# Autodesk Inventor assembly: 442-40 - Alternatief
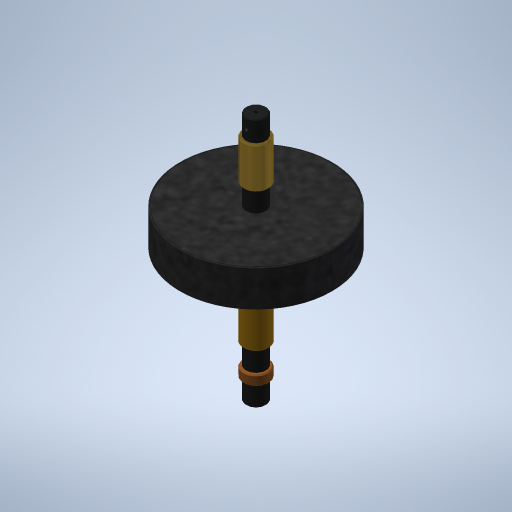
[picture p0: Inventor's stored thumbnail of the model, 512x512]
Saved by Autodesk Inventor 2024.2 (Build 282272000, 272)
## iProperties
Manager: Filip
Company: DARK
Created: 2022-10
Part Number: 442-40 - Alternatief
Document SubType Name: Assembly
Designer: Manuel
Engineer: Filip
Project: 442 - TOTM
Description: TOTM SMALL Assy
Author: Manuel
Revision Number: v0
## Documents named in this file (16)
- C:\Users\Stage\Desktop\Stage Karsten\armatures\TOTM - Wall\442_KARSTEN\3D_LIB_TOTM_2.iam
- C:\Users\Stage\Desktop\Stage Karsten\armatures\TOTM - Wall\442-042.ipt
- C:\Users\Stage\Desktop\Stage Karsten\armatures\TOTM - Wall\442-043.ipt
- C:\Users\Stage\Desktop\Stage Karsten\armatures\TOTM - Wall\442-044.ipt
- C:\Users\Stage\Desktop\Stage Karsten\armatures\TOTM - Wall\442-045.ipt
- C:\Users\Stage\Desktop\Stage Karsten\armatures\TOTM - Wall\442-048.ipt
- C:\Users\Stage\Desktop\Stage Karsten\armatures\TOTM - Wall\442-049.ipt
- C:\Users\Stage\Desktop\Stage Karsten\armatures\TOTM - Wall\442-050.ipt
- C:\Users\Stage\Desktop\Stage Karsten\armatures\TOTM - Wall\442-053.ipt
- C:\Users\Stage\Desktop\Stage Karsten\armatures\TOTM - Wall\442-054.ipt
- C:\Users\Stage\Desktop\Stage Karsten\armatures\TOTM - Wall\442-055.ipt
- C:\Users\Stage\Desktop\Stage Karsten\armatures\TOTM - Wall\442-056.ipt
- N:\LIBRARY\LAMPEN\LED\STARK CLE 120-2200 classic _ 16206616_00.ipt
- N:\LIBRARY\BEVESTIGING\DIN 912\DIN 912 M3 x 8.ipt
- N:\LIBRARY\BEVESTIGING\DIN 985\DIN 985 M3.ipt
- C:\Users\Stage\Desktop\Stage Karsten\armatures\TOTM - Wall\442-40 - Alternatief.iam
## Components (20 placed, 14 different names)
1. 442-042:1 — Mate:19, Mate:20, Mate:21, Mate:22
2. 442-043:1 — Mate:13, Mate:14, Mate:15, Mate:16
3. 442-044:1 — Mate:9, Mate:10, Mate:17, Mate:18
4. 442-045:1 — Mate:23, Mate:24, Mate:32, Mate:34
5. 442-048:1 — Mate:17, Mate:18, Mate:19, Mate:20
6. 442-049:1 — Mate:15, Mate:16
7. 442-050:1 — Mate:21, Mate:22, Mate:23, Mate:24
8. 442-048:2 — Mate:13, Mate:14, Mate:33, Mate:34, Mate:37
9. 442-048:3 — Mate:9, Mate:10, Mate:31
10. 442-053:1
11. 442-054:1 — Mate:28, Flush:1, Mate:31
12. 442-055:1
13. 442-056:1 — Mate:29, Mate:30, Mate:33, Flush:5, Flush:6, Flush:7
14. STARK CLE 120-2200 classic _ 16206616_00:1 — Mate:38, Mate:39, Flush:2, Mate:40
15. DIN 912 M3 x 8:1 — Flush:3, Mate:40, Mate:41, Mate:46
16. DIN 912 M3 x 8:2 — Flush:3, Flush:4, Mate:42, Mate:45
17. DIN 912 M3 x 8:3 — Flush:4, Mate:43, Mate:47
18. DIN 985 M3:1 — Flush:8, Mate:44, Mate:45
19. DIN 985 M3:2 — Flush:8, Flush:9, Mate:46
20. DIN 985 M3:3 — Flush:9, Mate:47
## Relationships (41: Mate 32, Flush 9)
- Mate:9: 442-044:1 ↔ 442-048:3
- Mate:10: 442-044:1 ↔ 442-048:3
- Mate:13: 442-043:1 ↔ 442-048:2
- Mate:14: 442-043:1 ↔ 442-048:2
- Mate:15: 442-043:1 ↔ 442-049:1
- Mate:16: 442-043:1 ↔ 442-049:1
- Mate:17: 442-044:1 ↔ 442-048:1
- Mate:18: 442-044:1 ↔ 442-048:1
- Mate:19: 442-042:1 ↔ 442-048:1
- Mate:20: 442-042:1 ↔ 442-048:1
- Mate:21: 442-042:1 ↔ 442-050:1
- Mate:22: 442-042:1 ↔ 442-050:1
- Mate:23: 442-045:1 ↔ 442-050:1
- Mate:24: 442-045:1 ↔ 442-050:1
- Mate:28: 442-054:1
- Flush:1: 442-054:1
- Mate:29: 442-056:1
- Mate:30: 442-056:1
- Mate:31: 442-048:3 ↔ 442-054:1
- Mate:32: 442-045:1
- Mate:33: 442-048:2 ↔ 442-056:1
- Mate:34: 442-045:1 ↔ 442-048:2
- Mate:37: 442-048:2
- Mate:38: STARK CLE 120-2200 classic _ 16206616_00:1
- Mate:39: STARK CLE 120-2200 classic _ 16206616_00:1
- Flush:2: STARK CLE 120-2200 classic _ 16206616_00:1
- Flush:3: DIN 912 M3 x 8:1 ↔ DIN 912 M3 x 8:2
- Flush:4: DIN 912 M3 x 8:2 ↔ DIN 912 M3 x 8:3
- Mate:40: STARK CLE 120-2200 classic _ 16206616_00:1 ↔ DIN 912 M3 x 8:1
- Mate:41: DIN 912 M3 x 8:1
- Mate:42: DIN 912 M3 x 8:2
- Mate:43: DIN 912 M3 x 8:3
- Flush:5: 442-056:1
- Flush:6: 442-056:1
- Flush:7: 442-056:1
- Flush:8: DIN 985 M3:1 ↔ DIN 985 M3:2
- Flush:9: DIN 985 M3:2 ↔ DIN 985 M3:3
- Mate:44: DIN 985 M3:1
- Mate:45: DIN 912 M3 x 8:2 ↔ DIN 985 M3:1
- Mate:46: DIN 912 M3 x 8:1 ↔ DIN 985 M3:2
- Mate:47: DIN 912 M3 x 8:3 ↔ DIN 985 M3:3
